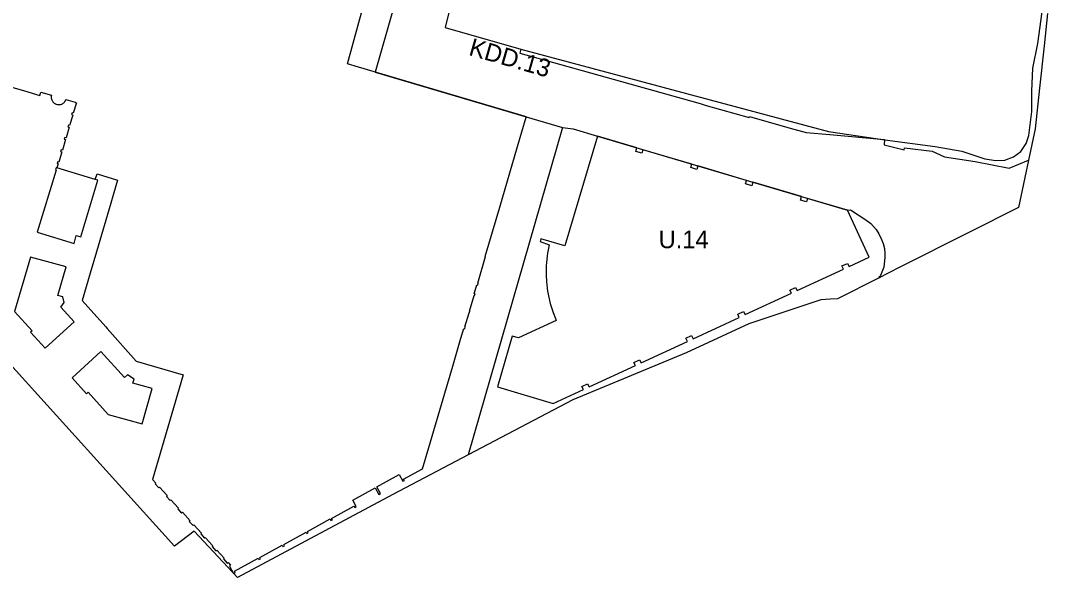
# Model space of a CAD drawing. Extents: x 7424052 to 7425705, y 5546602 to 5547569.
# Drawn here: x 7425164.6 to 7425455, y 5546760.2 to 5546917.7 of the extents above; entities that cross this region are included whole.
import ezdxf

# ---------------------------------------------------------------- set-up
doc = ezdxf.new("R2010")
doc.units = 0
for name, color, linetype in [('linie rozgraniczające', 7, 'Continuous'), ('nieprzekraczalne linie zabudowy', 7, 'Continuous'), ('obowiazujace linie zabudowy', 7, 'Continuous'), ('przeznaczenia terenów', 7, 'Continuous')]:
    doc.layers.add(name, color=color, linetype=linetype)

msp = doc.modelspace()

# ---------------------------------------------------------------- linework, layer by layer
at = {"layer": 'linie rozgraniczające'}
for p, q in [((7425288.06, 5546929.59), (7425284.64, 5546915.69)), ((7425271.28, 5546925.67), (7425264.86, 5546903.09)), ((7425454.97, 5546919.66), (7425454, 5546910.51)), ((7425284.64, 5546915.69), (7425306.05, 5546909.59)), ((7425454, 5546910.51), (7425452.74, 5546898.58)), ((7425306.05, 5546909.59), (7425305.78, 5546908.49)), ((7425305.78, 5546908.49), (7425317, 5546905.34)), ((7425317, 5546905.34), (7425356.72, 5546894.19)), ((7425264.86, 5546903.09), (7425307.53, 5546890.49)), ((7425452.74, 5546898.58), (7425451.52, 5546887.07)), ((7425356.72, 5546894.19), (7425358.5, 5546893.69)), ((7425358.5, 5546893.69), (7425370.64, 5546890.28)), ((7425307.53, 5546890.49), (7425317.83, 5546887.45)), ((7425370.64, 5546890.28), (7425370.67, 5546890.56)), ((7425370.67, 5546890.56), (7425382.21, 5546887.22)), ((7425317.83, 5546887.45), (7425291.13, 5546794.9)), ((7425317.83, 5546887.45), (7425320.86, 5546887.01)), ((7425320.86, 5546887.01), (7425327.69, 5546884.94)), ((7425327.69, 5546884.94), (7425398.44, 5546864.06)), ((7425382.21, 5546887.22), (7425386.78, 5546886.04)), ((7425386.78, 5546886.04), (7425393.41, 5546885.42)), ((7425393.41, 5546885.42), (7425408.88, 5546884.03)), ((7425408.88, 5546884.03), (7425408.75, 5546882.55)), ((7425408.75, 5546882.55), (7425414.49, 5546881.07)), ((7425414.49, 5546881.07), (7425414.58, 5546881.69)), ((7425414.58, 5546881.69), (7425422.35, 5546880.74)), ((7425422.35, 5546880.74), (7425425.89, 5546879.13)), ((7425425.89, 5546879.13), (7425434.51, 5546877.77)), ((7425434.51, 5546877.77), (7425444.17, 5546875.97)), ((7425444.17, 5546875.97), (7425449.62, 5546878.21)), ((7425449.62, 5546878.21), (7425446.75, 5546864.78)), ((7425398.44, 5546864.06), (7425399.27, 5546864.12)), ((7425399.27, 5546864.12), (7425401.44, 5546862.7)), ((7425446.75, 5546864.78), (7425432.71, 5546857.71)), ((7425401.44, 5546862.7), (7425403.62, 5546861.28)), ((7425403.62, 5546861.28), (7425405.03, 5546860.24)), ((7425405.03, 5546860.24), (7425405.77, 5546859.4)), ((7425405.77, 5546859.4), (7425406.51, 5546858.56)), ((7425406.51, 5546858.56), (7425407.26, 5546857.4)), ((7425407.26, 5546857.4), (7425407.6, 5546856.72)), ((7425407.6, 5546856.72), (7425407.95, 5546856.04)), ((7425407.95, 5546856.04), (7425408.24, 5546855.32)), ((7425408.24, 5546855.32), (7425408.53, 5546854.6)), ((7425432.71, 5546857.71), (7425413.05, 5546847.81)), ((7425408.53, 5546854.6), (7425408.93, 5546853.26)), ((7425408.93, 5546853.26), (7425408.98, 5546851.84)), ((7425409.01, 5546850.7), (7425408.74, 5546847.93)), ((7425408.98, 5546851.84), (7425409.01, 5546850.7)), ((7425413.05, 5546847.81), (7425407.2, 5546844.87)), ((7425408.74, 5546847.93), (7425407.73, 5546845.59)), ((7425407.73, 5546845.59), (7425407.2, 5546844.87)), ((7425390.91, 5546838.71), (7425370.5, 5546831.95)), ((7425393.51, 5546838.88), (7425390.91, 5546838.71)), ((7425208.12, 5546769.05), (7425153.43, 5546829.48)), ((7425370.5, 5546831.95), (7425352.83, 5546823.71)), ((7425352.83, 5546823.71), (7425320.74, 5546810.47)), ((7425320.74, 5546810.47), (7425291.13, 5546794.9)), ((7425291.13, 5546794.9), (7425269.84, 5546783.7)), ((7425269.84, 5546783.7), (7425225.89, 5546760.2)), ((7425213.67, 5546773.31), (7425208.12, 5546769.05)), ((7425225.89, 5546760.2), (7425213.67, 5546773.31))]:
    msp.add_line(p, q, dxfattribs=at)
for points in [[(7425451.52, 5546887.07), (7425449.62, 5546878.21), (7425449.62, 5546878.21)], [(7425407.5, 5546845.27), (7425407.2, 5546844.87), (7425395.55, 5546839), (7425393.51, 5546838.88)]]:
    msp.add_lwpolyline(points, dxfattribs=at)
at = {"layer": 'nieprzekraczalne linie zabudowy'}
for p, q in [((7425288.06, 5546929.59), (7425284.64, 5546915.69)), ((7425452.26, 5546911.19), (7425453.8, 5546922.24)), ((7425284.64, 5546915.69), (7425306.05, 5546909.59)), ((7425450.88, 5546904.22), (7425452.26, 5546911.19)), ((7425306.05, 5546909.59), (7425393.03, 5546886.27)), ((7425450.56, 5546897.66), (7425450.88, 5546904.22)), ((7425450.57, 5546891.96), (7425450.56, 5546897.66)), ((7425449.68, 5546885.18), (7425450.57, 5546891.96)), ((7425393.03, 5546886.27), (7425409.01, 5546883.96)), ((7425448.99, 5546882.86), (7425449.68, 5546885.18)), ((7425409.01, 5546883.96), (7425423.24, 5546882.08)), ((7425423.24, 5546882.08), (7425430.71, 5546880.73)), ((7425447.46, 5546880.66), (7425448.99, 5546882.86)), ((7425430.71, 5546880.73), (7425437.22, 5546878.57)), ((7425437.22, 5546878.57), (7425440.35, 5546878.12)), ((7425442.93, 5546878.22), (7425445.36, 5546879.12)), ((7425445.36, 5546879.12), (7425447.46, 5546880.66)), ((7425440.35, 5546878.12), (7425442.93, 5546878.22))]:
    msp.add_line(p, q, dxfattribs=at)
at = {"layer": 'obowiazujace linie zabudowy'}
for p, q in [((7425327.69, 5546884.94), (7425318.5, 5546853.97)), ((7425338.82, 5546881.64), (7425327.69, 5546884.94)), ((7425338.54, 5546880.68), (7425338.82, 5546881.64)), ((7425340.26, 5546880.17), (7425338.54, 5546880.68)), ((7425340.54, 5546881.14), (7425340.26, 5546880.17)), ((7425354.36, 5546877.05), (7425340.54, 5546881.14)), ((7425354.08, 5546876.09), (7425354.36, 5546877.05)), ((7425355.78, 5546875.59), (7425354.08, 5546876.09)), ((7425356.07, 5546876.56), (7425355.78, 5546875.59)), ((7425369.9, 5546872.47), (7425356.07, 5546876.56)), ((7425369.61, 5546871.49), (7425369.9, 5546872.47)), ((7425371.34, 5546870.98), (7425369.61, 5546871.49)), ((7425371.62, 5546871.94), (7425371.34, 5546870.98)), ((7425385.43, 5546867.88), (7425371.62, 5546871.94)), ((7425385.15, 5546866.91), (7425385.43, 5546867.88)), ((7425387.15, 5546867.37), (7425386.87, 5546866.41)), ((7425398.44, 5546864.06), (7425387.15, 5546867.37)), ((7425386.87, 5546866.41), (7425385.15, 5546866.91)), ((7425404.58, 5546850.76), (7425398.44, 5546864.06)), ((7425311.7, 5546855.94), (7425311.48, 5546855.18)), ((7425318.5, 5546853.97), (7425311.7, 5546855.94)), ((7425311.48, 5546855.18), (7425314.08, 5546854.3)), ((7425313.97, 5546853.78), (7425313.62, 5546851.92)), ((7425314.08, 5546854.3), (7425313.97, 5546853.78)), ((7425313.51, 5546851.17), (7425313.29, 5546849.21)), ((7425313.62, 5546851.92), (7425313.51, 5546851.17)), ((7425398.86, 5546848.12), (7425404.58, 5546850.76)), ((7425313.22, 5546847.6), (7425313.17, 5546845.69)), ((7425313.25, 5546848.45), (7425313.22, 5546847.6)), ((7425313.29, 5546849.21), (7425313.25, 5546848.45)), ((7425384.18, 5546841.31), (7425397.25, 5546847.34)), ((7425396.82, 5546848.27), (7425398.45, 5546849.02)), ((7425397.25, 5546847.34), (7425396.82, 5546848.27)), ((7425398.45, 5546849.02), (7425398.86, 5546848.12)), ((7425313.17, 5546845.69), (7425313.26, 5546843.9)), ((7425313.26, 5546843.9), (7425313.51, 5546842.01)), ((7425313.51, 5546842.01), (7425313.62, 5546841.16)), ((7425313.62, 5546841.16), (7425313.79, 5546840.31)), ((7425382.13, 5546841.46), (7425383.76, 5546842.21)), ((7425382.55, 5546840.55), (7425382.13, 5546841.46)), ((7425383.76, 5546842.21), (7425384.18, 5546841.31)), ((7425313.79, 5546840.31), (7425314.16, 5546838.55)), ((7425314.16, 5546838.55), (7425314.38, 5546837.67)), ((7425369.46, 5546834.51), (7425382.55, 5546840.55)), ((7425314.38, 5546837.67), (7425314.9, 5546835.94)), ((7425314.9, 5546835.94), (7425315.18, 5546835.13)), ((7425315.18, 5546835.13), (7425315.85, 5546833.4)), ((7425367.4, 5546834.65), (7425369.05, 5546835.41)), ((7425369.05, 5546835.41), (7425369.46, 5546834.51)), ((7425316.08, 5546832.87), (7425305.34, 5546827.93)), ((7425315.85, 5546833.4), (7425316.08, 5546832.87)), ((7425354.76, 5546827.7), (7425367.83, 5546833.74)), ((7425367.83, 5546833.74), (7425367.4, 5546834.65)), ((7425303.64, 5546828.43), (7425299.4, 5546814.06)), ((7425305.34, 5546827.93), (7425303.64, 5546828.43)), ((7425340.05, 5546820.87), (7425353.16, 5546826.94)), ((7425352.74, 5546827.86), (7425354.34, 5546828.6)), ((7425353.16, 5546826.94), (7425352.74, 5546827.86)), ((7425354.34, 5546828.6), (7425354.76, 5546827.7)), ((7425338.02, 5546821.02), (7425339.64, 5546821.77)), ((7425338.43, 5546820.14), (7425338.02, 5546821.02)), ((7425339.64, 5546821.77), (7425340.05, 5546820.87)), ((7425325.35, 5546814.07), (7425338.43, 5546820.14)), ((7425323.3, 5546814.21), (7425324.94, 5546814.96)), ((7425324.94, 5546814.96), (7425325.35, 5546814.07)), ((7425299.4, 5546814.06), (7425315.23, 5546809.4)), ((7425315.23, 5546809.4), (7425323.72, 5546813.31)), ((7425323.72, 5546813.31), (7425323.3, 5546814.21))]:
    msp.add_line(p, q, dxfattribs=at)
for points in [[(7425185.71, 5546872.75), (7425186.2, 5546874.32), (7425191.99, 5546872.56), (7425191.52, 5546870.96), (7425190.07, 5546866.01), (7425186.03, 5546852.28), (7425184.25, 5546846.21), (7425181.99, 5546838.55), (7425188.67, 5546831.04), (7425189.06, 5546830.59), (7425197.23, 5546821.4), (7425210.6, 5546817.47), (7425201.84, 5546787.89), (7425202.83, 5546786.86), (7425202.61, 5546786.67), (7425203.66, 5546785.5), (7425203.89, 5546785.7), (7425206.05, 5546783.33), (7425205.83, 5546783.13), (7425206.89, 5546781.95), (7425207.11, 5546782.15), (7425209.26, 5546779.78), (7425209.04, 5546779.57), (7425210.13, 5546778.41), (7425210.34, 5546778.62), (7425212.5, 5546776.22), (7425212.28, 5546776.01), (7425213.36, 5546774.86), (7425213.57, 5546775.07), (7425215.74, 5546772.7), (7425215.51, 5546772.51), (7425216.58, 5546771.28), (7425216.8, 5546771.48), (7425218.97, 5546769.12), (7425218.75, 5546768.92), (7425219.81, 5546767.73), (7425220.04, 5546767.93), (7425222.18, 5546765.62), (7425221.96, 5546765.42), (7425223.03, 5546764.21), (7425223.26, 5546764.42), (7425223.93, 5546763.66), (7425223.69, 5546763.43), (7425224.82, 5546761.34), (7425225.3, 5546761.6), (7425225.09, 5546761.97), (7425231.76, 5546765.66), (7425231.96, 5546765.24), (7425232.43, 5546765.46), (7425232.23, 5546765.88), (7425238.55, 5546769.33), (7425238.74, 5546768.92), (7425239.2, 5546769.14), (7425239, 5546769.55), (7425245.3, 5546773.01), (7425245.5, 5546772.59), (7425245.95, 5546772.81), (7425245.74, 5546773.21), (7425252.08, 5546776.73), (7425252.29, 5546776.29), (7425252.75, 5546776.51), (7425252.52, 5546776.91), (7425258.85, 5546780.4), (7425259.12, 5546779.97), (7425259.52, 5546780.22), (7425258.5, 5546782.07), (7425264.86, 5546785.56), (7425265.9, 5546783.67), (7425266.34, 5546783.91), (7425265.3, 5546785.8), (7425271.67, 5546789.3), (7425272.72, 5546787.39), (7425273.14, 5546787.63), (7425272.91, 5546788.04), (7425278.2, 5546790.9), (7425280, 5546796.99), (7425284.52, 5546812.31), (7425286.79, 5546819.96), (7425289.12, 5546827.87), (7425289.93, 5546830.62), (7425290.18, 5546830.54), (7425290.33, 5546831.02), (7425290.22, 5546831.05), (7425291.39, 5546835.01), (7425291.51, 5546834.98), (7425291.64, 5546835.45), (7425291.52, 5546835.49), (7425292.84, 5546839.91), (7425292.95, 5546839.88), (7425293.09, 5546840.37), (7425292.89, 5546840.43), (7425293.64, 5546842.91), (7425293.84, 5546842.85), (7425293.98, 5546843.34), (7425293.87, 5546843.38), (7425296.08, 5546850.91), (7425295.93, 5546850.96), (7425300.07, 5546864.95), (7425305.12, 5546882.1), (7425307.56, 5546890.37), (7425307.5, 5546890.39), (7425307.53, 5546890.49), (7425306.99, 5546890.64), (7425260.14, 5546904.48), (7425257.02, 5546905.42), (7425262.9, 5546926.87)], [(7425159.06, 5546899.72), (7425165.39, 5546897.85), (7425170.05, 5546896.48), (7425170.33, 5546897.46), (7425173.29, 5546896.55), (7425173.25, 5546896.32), (7425173.23, 5546896.1), (7425173.25, 5546895.77), (7425173.29, 5546895.54), (7425173.38, 5546895.27), (7425173.49, 5546895.03), (7425173.6, 5546894.86), (7425173.68, 5546894.73), (7425173.82, 5546894.58), (7425173.93, 5546894.47), (7425174.09, 5546894.33), (7425174.24, 5546894.23), (7425174.41, 5546894.13), (7425174.56, 5546894.07), (7425174.67, 5546894.02), (7425174.88, 5546893.96), (7425175.09, 5546893.92), (7425175.31, 5546893.9), (7425175.55, 5546893.91), (7425175.81, 5546893.94), (7425175.98, 5546893.98), (7425176.2, 5546894.06), (7425176.39, 5546894.15), (7425176.6, 5546894.27), (7425176.8, 5546894.42), (7425176.98, 5546894.6), (7425176.99, 5546894.61), (7425177.12, 5546894.77), (7425177.23, 5546894.94), (7425177.33, 5546895.11), (7425177.41, 5546895.31), (7425180.03, 5546894.58), (7425180.01, 5546894.5), (7425180.35, 5546894.39), (7425179.48, 5546891.45), (7425179.14, 5546891.54), (7425178.99, 5546891.06), (7425179.34, 5546890.96), (7425178.46, 5546887.98), (7425178.11, 5546888.08), (7425178.04, 5546887.82), (7425177.97, 5546887.59), (7425178.32, 5546887.5), (7425177.44, 5546884.51), (7425177.09, 5546884.62), (7425176.94, 5546884.12), (7425177.29, 5546884.01), (7425176.41, 5546881.03), (7425176.06, 5546881.13), (7425175.91, 5546880.64), (7425176.26, 5546880.54), (7425175.41, 5546877.66), (7425175.06, 5546877.76), (7425174.92, 5546877.27), (7425175.17, 5546877.2), (7425174.8, 5546875.98)], [(7425186.43, 5546872.52), (7425185.71, 5546872.75), (7425174.8, 5546875.98), (7425174.68, 5546876.01), (7425174.5, 5546875.43), (7425174.6, 5546875.38), (7425169.29, 5546857.8), (7425179.73, 5546854.62), (7425180.34, 5546856.88), (7425181.66, 5546856.5), (7425186.43, 5546872.52)], [(7425167.41, 5546850.8), (7425162.88, 5546835.39), (7425167.84, 5546829.96), (7425167.4, 5546829.56), (7425171.49, 5546825.07), (7425179.69, 5546832.5), (7425175.93, 5546836.6), (7425176.92, 5546837.91), (7425176.51, 5546839.51), (7425175.13, 5546839.89), (7425177.45, 5546848.01), (7425167.41, 5546850.8)], [(7425196.73, 5546816.25), (7425194.83, 5546817.46), (7425194, 5546816.7), (7425187.27, 5546824.13), (7425179.14, 5546816.65), (7425183.21, 5546812.15), (7425183.65, 5546812.55), (7425189.34, 5546806.28), (7425198.94, 5546803.6), (7425201.75, 5546813.67), (7425196.36, 5546815.13), (7425196.73, 5546816.25)]]:
    msp.add_lwpolyline(points, dxfattribs=at)

# ---------------------------------------------------------------- texts
at = {"layer": 'przeznaczenia terenów'}
msp.add_text('KDD.13', height=5, rotation=344, dxfattribs=at).set_placement((7425291.06, 5546907.98))
msp.add_text('U.14', height=5, dxfattribs=at).set_placement((7425345.02, 5546853.3))

doc.saveas('drawing.dxf')
